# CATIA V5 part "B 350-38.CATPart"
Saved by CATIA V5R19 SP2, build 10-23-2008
Part number: B 350-38
Bounding box of the stored display mesh (mm): x -15.868 to 15.868, y -15.868 to 15.868, z 0 to 126
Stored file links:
  C:\Users\Bora\Desktop\3D Katı model\B serisi\B 350\B 350-38.CATPart
  C:\Program Files\Dassault Systemes\B19\intel_a\reffiles\standard\MetricThickPitch.txt
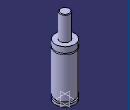
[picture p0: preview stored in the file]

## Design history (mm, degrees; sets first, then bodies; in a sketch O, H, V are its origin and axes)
Body1 (main body)
  Sketch1 on yz-plane, origin (0, 0, 0), H (0, 1, 0), V (0, 0, 1)
    point P3 (8, 125)
    point P5 (8, 125)
    point P7 (16, 76.5)
    point P8 (16, 74.5)
    point P12 (16, 74.5)
    point P13 (16, 76.5)
    line L1 (16, 0) -> (16, 4)
    line L2 (8, 125) -> (8, 86)
    arc A1 centre (7, 125) radius 1 from (8, 125) to (7, 126) ccw
    arc A2 centre (16, 75.5) radius 1 from (16, 76.5) to (16, 74.5) ccw
    line L3 (13.5, 7.5) -> (13.5, 4)
    line L4 (16, 7.5) -> (16, 74.5)
    line L5 (16, 76.5) -> (16, 86)
    line L6 (7, 126) -> (0, 126)
    point P15 (0, 126)
    line L7 (8, 86) -> (16, 86)
    line L8 (0, 0) -> (16, 0)
    line L9 (13.5, 7.5) -> (16, 7.5)
    line L10 (13.5, 4) -> (16, 4)
    coincidence: P15 V, P3 P5, P7 P13, P8 P12
    tangency: L6 A1
    horizontal: L7 H, L8 H, L9 H, L10 H
  Shaft1: profile Sketch1, axis Sketch1.V, angle 360
  Sketch2 on face of Shaft1 from Sketch1.L8, origin (0, 0, 0), H (1, 0, 0), V (0, -1, 0)
    point P1 (0, 0)
  Hole1: placed by Sketch2, at (0, 0, 0) direction (0, 0, 1), diameter 6.647, depth 7, threaded "M8", thread diameter 8, thread depth 7, pitch 1.25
